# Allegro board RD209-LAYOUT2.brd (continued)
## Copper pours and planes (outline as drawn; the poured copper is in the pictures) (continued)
GND on TOP: outline of 2710 points within 0.43,0.41 198.5,157.02 ; 35 cut-outs
GND on TOP: 190.48,67.77 190.44,67.82 190.44,67.87 190.67,68.44 190.67,68.44 191.99,71.08 191.99,71.08 192.41,71.81 192.45,71.84 192.51,71.84 196.23,70.03 196.83,69.74 196.86,69.7 196.86,69.64 195.02,65.71 194.98,65.68 194.92,65.68
GND on TOP: 154.03,84.98 154,85.02 154,85.08 155.97,89.07 156.01,89.11 156.06,89.11 160.19,87.14 160.22,87.1 160.22,87.04 158.38,82.99 158.34,82.95 158.28,82.95
GND on TOP: 102.3,31.89 102.27,31.89 102.24,31.91 101.81,32.34 101.8,32.36 101.79,32.39 101.79,33.99 101.8,34.02 101.81,34.05 108.6,40.84 108.63,40.85 108.66,40.86 114.51,40.86 114.56,40.84 114.59,40.78 114.59,40.66 114.58,40.63 114.56,40.61 105.87,31.91 105.84,31.89 105.81,31.89 104.59,31.89 104.53,31.91 104.51,31.98 104.52,32.03 104.52,32.19 104.44,32.38 104.24,32.46 103.94,32.46 103.86,32.45 103.76,32.39 103.73,32.39 103.42,32.39 103.38,32.38 103.32,32.37 102.4,32.37 102.4,31.96 102.38,31.91 102.33,31.89
GND on TOP: 142.3,29.98 142.27,29.99 142.25,30 140.45,31.81 140.36,31.87 140.25,31.89 137.61,31.89 137.55,31.91 137.53,31.98 137.54,32.03 137.54,32.19 137.46,32.38 137.26,32.46 136.97,32.46 136.88,32.45 136.78,32.39 136.75,32.39 135.42,32.39 135.42,31.96 135.4,31.91 135.35,31.89 135.32,31.89 135.29,31.89 135.26,31.91 134.83,32.34 134.82,32.36 134.81,32.39 134.81,35.27 134.82,35.3 134.83,35.33 136.53,37.03 136.56,37.04 136.59,37.05 147.41,37.05 147.47,37.03 147.49,36.97 147.49,36.74 147.48,36.72 147.47,36.69 145.05,34.28 145.05,31.12 145.05,31.09 145.03,31.07 143.97,30 143.94,29.99 143.91,29.98
GND on BOTTOM: 0.43,116.42 0.43,116.45 0.43,116.47 19.63,156.98 19.67,157.02 19.73,157.02 204.21,69.57 204.25,69.53 204.25,69.47 174.35,6.38 174.32,6.35 174.28,6.34 99.98,0.41 99.95,0.42 19.31,38.63 19.28,38.65 19.27,38.68 ; 364 cut-outs
LED+1 on TOP: 108.5,22.09 108.5,27.48 112.94,27.48 112.94,22.09
LED+1 on TOP, CONDUCTIVE3: 70.72,66.22 70.72,70.34 77.07,70.34 77.07,66.22
LED+1 on CONDUCTIVE3: 108.5,22.09 108.5,27.48 112.87,27.48 112.87,22.09
LED+2 on TOP: 66.59,72.25 66.59,76.38 71.03,76.38 71.03,72.25
LED+2 on TOP: 74.21,22.09 74.21,27.48 79.92,27.48 79.92,22.09
LED+2 on BOTTOM: 74.28,22.09 74.23,22.11 74.21,22.16 74.21,27.41 74.23,27.46 74.28,27.48 78.26,27.48 78.32,27.46 78.34,27.41 78.34,22.16 78.32,22.11 78.26,22.09
LED+2 on BOTTOM: 66.66,72.25 66.61,72.27 66.59,72.32 66.59,75.67 66.61,75.72 66.66,75.74 70.96,75.74 71.01,75.72 71.03,75.67 71.03,72.32 71.01,72.27 70.96,72.25
LED+3 on TOP: 17.7,53.2 17.7,63.04 24.04,63.04 24.04,57.65 22.14,57.65 22.14,53.2
LED+3 on TOP, CONDUCTIVE2: 60.56,78.28 60.56,82.41 65,82.41 65,78.28
LED+3 on CONDUCTIVE2: 17.7,53.2 17.7,57.33 22.14,57.33 22.14,53.2
LED+4 on TOP: 54.53,84.31 54.53,88.44 58.97,88.44 58.97,84.31
LED+4 on TOP: 11.34,77.33 11.34,87.17 17.7,87.17 17.7,81.77 15.79,81.77 15.79,77.33
LED+4 on BOTTOM: 54.85,84.57 54.8,84.59 54.78,84.64 54.78,88.11 54.8,88.17 54.85,88.19 58.64,88.19 58.69,88.17 58.72,88.11 58.72,84.64 58.69,84.59 58.64,84.57
LED+4 on BOTTOM: 11.42,77.33 11.37,77.35 11.34,77.4 11.34,81.38 11.37,81.44 11.42,81.46 15.71,81.46 15.77,81.44 15.79,81.38 15.79,77.4 15.77,77.35 15.71,77.33
LED+5 on TOP: 48.49,90.35 48.49,94.47 52.94,94.47 52.94,90.35
LED+5 on TOP, BOTTOM: 5.63,108.44 5.63,113.84 10.07,113.84 10.07,108.44
LED+5 on BOTTOM: 48.49,90.35 48.49,94.47 51.67,94.47 51.67,90.35
LED+6 on TOP, CONDUCTIVE2: 42.46,96.38 42.46,100.51 46.91,100.51 46.91,96.38
LED+6 on TOP, CONDUCTIVE2: 11.98,135.12 11.98,140.51 16.43,140.51 16.43,135.12
LED+7 on TOP, CONDUCTIVE2: 141.52,22.09 141.52,27.48 145.97,27.48 145.97,22.09
LED+7 on TOP, CONDUCTIVE2: 90.72,46.53 90.72,50.66 95.16,50.66 95.16,46.53
LED-1 on TOP: 137.39,17.64 137.39,21.45 143.74,21.45 143.74,17.64
LED-1 on TOP, CONDUCTIVE3: 137.71,66.22 137.71,70.34 142.16,70.34 142.16,66.22
LED-1 on CONDUCTIVE3: 137.39,17.64 137.39,21.45 141.84,21.45 141.84,17.64
LED-2 on TOP: 131.68,72.25 131.68,76.38 136.12,76.38 136.12,72.25
LED-2 on TOP: 104.37,17.64 104.37,21.45 110.72,21.45 110.72,17.64
LED-2 on BOTTOM: 104.69,17.64 104.69,21.45 108.5,21.45 108.5,17.64
LED-2 on BOTTOM: 131.68,72.25 131.68,75.74 136.12,75.74 136.12,72.25
LED-3 on TOP, CONDUCTIVE2: 125.65,78.28 125.65,82.41 130.09,82.41 130.09,78.28
LED-3 on TOP, CONDUCTIVE2: 48.49,53.2 48.49,57.01 52.94,57.01 52.94,53.2
LED-4 on TOP: 42.14,77.33 42.14,81.14 48.49,81.14 48.49,77.33
LED-4 on TOP: 119.61,84.31 119.61,88.44 124.06,88.44 124.06,84.31
LED-4 on BOTTOM: 119.69,84.31 119.63,84.34 119.61,84.39 119.61,88.37 119.63,88.42 119.69,88.44 123.98,88.44 124.04,88.42 124.06,88.37 124.06,84.39 124.04,84.34 123.98,84.31
LED-4 on BOTTOM: 42.22,77.33 42.16,77.35 42.14,77.4 42.14,79.79 42.16,79.85 42.22,79.87 47.47,79.87 47.52,79.85 47.54,79.79 47.54,77.4 47.52,77.35 47.47,77.33
LED-5 on TOP, BOTTOM: 113.58,90.35 113.58,94.47 118.02,94.47 118.02,90.35
LED-5 on TOP, CONDUCTIVE3: 34.52,104 34.52,107.81 38.97,107.81 38.97,104
LED-6 on TOP: 40.87,130.67 40.87,134.48 47.22,134.48 47.22,130.67
LED-6 on TOP, CONDUCTIVE2: 107.55,96.38 107.55,100.51 111.99,100.51 111.99,96.38
LED-6 on CONDUCTIVE2: 40.87,130.67 40.87,134.48 45.32,134.48 45.32,130.67
LED-7 on TOP, CONDUCTIVE2: 153.27,46.53 153.27,50.66 157.71,50.66 157.71,46.53
LED-7 on TOP, CONDUCTIVE2: 170.41,17.64 170.41,21.45 174.86,21.45 174.86,17.64
N_16 on TOP: 111.99,17.64 111.99,21.45 115.48,21.45 115.48,27.48 118.34,27.48 118.34,22.09 116.44,22.09 116.44,17.64
N_16 on TOP, CONDUCTIVE3: 77.7,66.22 77.7,70.34 89.13,70.34 89.13,66.22
N_16 on CONDUCTIVE3: 111.99,17.64 111.99,21.45 116.44,21.45 116.44,17.64
N_20 on TOP: 117.07,17.64 117.07,21.45 120.56,21.45 120.56,27.48 123.42,27.48 123.42,22.09 121.52,22.09 121.52,17.64
N_20 on TOP, CONDUCTIVE3: 89.77,66.22 89.77,70.34 101.2,70.34 101.2,66.22
N_20 on CONDUCTIVE3: 117.07,17.64 117.07,21.45 121.52,21.45 121.52,17.64
N_23 on TOP: 122.15,17.64 122.15,21.45 125.65,21.45 125.65,27.48 128.5,27.48 128.5,22.09 126.6,22.09 126.6,17.64
N_23 on TOP, CONDUCTIVE3: 101.83,66.22 101.83,70.34 113.26,70.34 113.26,66.22
N_23 on CONDUCTIVE3: 122.15,17.64 122.15,21.45 126.6,21.45 126.6,17.64
N_26 on TOP: 127.23,17.64 127.23,21.45 130.72,21.45 130.72,27.48 133.58,27.48 133.58,22.09 131.68,22.09 131.68,17.64
N_26 on TOP, CONDUCTIVE3: 113.9,66.22 113.9,70.34 125.01,70.34 125.01,66.22
N_26 on CONDUCTIVE3: 127.23,17.64 127.23,21.45 131.68,21.45 131.68,17.64
N_29 on TOP: 71.67,72.25 71.67,76.38 83.1,76.38 83.1,72.25
N_29 on TOP: 78.97,17.64 78.97,21.45 82.47,21.45 82.47,27.48 85.32,27.48 85.32,22.09 83.42,22.09 83.42,17.64
N_29 on BOTTOM: 71.67,72.25 71.67,75.74 81.83,75.74 81.83,72.25
N_29 on BOTTOM: 79.29,17.64 79.29,21.45 83.1,21.45 83.1,17.64
N_30 on TOP: 132.31,17.64 132.31,21.45 135.81,21.45 135.81,27.48 138.66,27.48 138.66,22.09 136.76,22.09 136.76,17.64
N_30 on TOP, CONDUCTIVE3: 125.65,66.22 125.65,70.34 137.07,70.34 137.07,66.22
N_30 on CONDUCTIVE3: 132.31,17.64 132.31,21.45 136.76,21.45 136.76,17.64
N_39 on TOP: 84.05,17.64 84.05,21.45 87.55,21.45 87.55,27.48 90.4,27.48 90.4,22.09 88.5,22.09 88.5,17.64
N_39 on TOP: 83.73,72.25 83.73,76.38 95.16,76.38 95.16,72.25
N_39 on BOTTOM: 84.37,17.64 84.37,21.45 88.18,21.45 88.18,17.64
N_39 on BOTTOM: 85,72.25 85,75.74 93.89,75.74 93.89,72.25
N_42 on TOP: 89.13,17.64 89.13,21.45 92.62,21.45 92.62,27.48 95.48,27.48 95.48,22.09 93.58,22.09 93.58,17.64
N_42 on TOP: 95.8,72.25 95.8,76.38 107.23,76.38 107.23,73.14 107.22,73.08 107.22,72.25
N_42 on BOTTOM: 89.45,17.64 89.45,21.45 93.26,21.45 93.26,17.64
N_42 on BOTTOM: 95.8,72.25 95.8,75.74 105.96,75.74 105.96,72.25
N_45 on TOP: 107.86,72.25 107.86,76.38 118.98,76.38 118.98,72.25
N_45 on TOP: 94.21,17.64 94.21,21.45 97.7,21.45 97.7,27.48 100.56,27.48 100.56,22.09 98.66,22.09 98.66,17.64
N_45 on BOTTOM: 109.13,72.25 109.13,75.74 118.34,75.74 118.34,72.25
N_45 on BOTTOM: 94.53,17.64 94.53,21.45 98.34,21.45 98.34,17.64
N_48 on TOP: 99.29,17.64 99.29,21.45 102.78,21.45 102.78,27.48 105.64,27.48 105.64,22.09 103.74,22.09 103.74,17.64
N_48 on TOP: 119.61,72.25 119.61,76.38 131.04,76.38 131.04,72.25
N_48 on BOTTOM: 120.25,72.25 120.25,75.74 130.41,75.74 130.41,72.25
N_48 on BOTTOM: 99.61,17.64 99.61,21.45 103.42,21.45 103.42,17.64
N_57 on TOP: 23.09,53.2 23.09,57.01 26.58,57.01 26.58,63.04 29.44,63.04 29.44,57.65 27.54,57.65 27.54,53.2
N_57 on TOP, CONDUCTIVE2: 65.64,78.28 65.64,82.41 77.07,82.41 77.07,78.28
N_57 on CONDUCTIVE2: 23.09,53.2 23.09,57.01 27.54,57.01 27.54,53.2
N_60 on TOP: 28.17,53.2 28.17,57.01 31.67,57.01 31.67,63.04 34.52,63.04 34.52,57.65 32.62,57.65 32.62,53.2
N_60 on TOP, CONDUCTIVE2: 77.7,78.28 77.7,82.41 89.13,82.41 89.13,78.28
N_60 on CONDUCTIVE2: 28.17,53.2 28.17,57.01 32.62,57.01 32.62,53.2
N_63 on TOP: 89.77,78.28 89.77,82.41 101.2,82.41 101.2,79.22 101.19,79.21 101.17,79.15 101.16,79.08 101.16,78.28
N_63 on TOP: 33.25,53.2 33.25,57.01 36.75,57.01 36.75,63.04 39.6,63.04 39.6,57.65 37.7,57.65 37.7,53.2
N_63 on CONDUCTIVE2: 33.25,53.2 33.25,57.01 37.7,57.01 37.7,53.2
N_63 on CONDUCTIVE2: 89.77,78.28 89.77,82.41 101.2,82.41 101.2,78.28
N_66 on TOP: 38.33,53.2 38.33,57.01 41.83,57.01 41.83,63.04 44.68,63.04 44.68,57.65 42.78,57.65 42.78,53.2
N_66 on TOP, CONDUCTIVE2: 101.83,78.28 101.83,82.41 112.94,82.41 112.94,78.28
N_66 on CONDUCTIVE2: 38.33,53.2 38.33,57.01 42.78,57.01 42.78,53.2
N_69 on TOP: 43.41,53.2 43.41,57.01 46.91,57.01 46.91,63.04 49.76,63.04 49.76,57.65 47.86,57.65 47.86,53.2
N_69 on TOP, CONDUCTIVE2: 113.58,78.28 113.58,82.41 125.01,82.41 125.01,78.28
N_69 on CONDUCTIVE2: 43.41,53.2 43.41,57.01 47.86,57.01 47.86,53.2
N_78 on TOP: 16.74,77.33 16.74,81.14 20.23,81.14 20.23,87.17 23.09,87.17 23.09,81.77 21.19,81.77 21.19,77.33
N_78 on TOP, CONDUCTIVE3: 59.6,84.31 59.6,88.44 71.03,88.44 71.03,84.31
N_78 on CONDUCTIVE3: 16.74,77.33 16.74,81.14 21.19,81.14 21.19,77.33
N_81 on TOP: 71.67,84.31 71.67,88.44 83.1,88.44 83.1,85.14 83.09,85.08 83.09,84.31
N_81 on TOP: 21.82,77.33 21.82,81.14 25.32,81.14 25.32,87.17 28.17,87.17 28.17,81.77 26.27,81.77 26.27,77.33
N_81 on CONDUCTIVE2: 71.67,84.31 71.67,88.44 83.1,88.44 83.1,84.31
N_81 on CONDUCTIVE2: 21.82,77.33 21.82,81.14 26.27,81.14 26.27,77.33
N_84 on TOP: 83.73,84.31 83.73,88.44 95.16,88.44 95.16,85.26 95.11,85.18 95.09,85.08 95.09,84.31
N_84 on TOP: 26.9,77.33 26.9,81.14 30.39,81.14 30.39,87.17 33.25,87.17 33.25,81.77 31.35,81.77 31.35,77.33
N_84 on BOTTOM: 26.98,77.33 26.92,77.35 26.9,77.4 26.9,81.06 26.92,81.12 26.98,81.14 31.27,81.14 31.33,81.12 31.35,81.06 31.35,77.4 31.33,77.35 31.27,77.33
N_87 on TOP: 31.98,77.33 31.98,81.14 35.47,81.14 35.47,87.17 38.33,87.17 38.33,81.77 36.43,81.77 36.43,77.33
N_87 on TOP, CONDUCTIVE2: 95.8,84.31 95.8,88.44 106.91,88.44 106.91,84.31
N_87 on CONDUCTIVE3: 31.98,77.33 31.98,81.14 36.43,81.14 36.43,77.33
N_90 on TOP: 37.06,77.33 37.06,81.14 40.56,81.14 40.56,87.17 43.41,87.17 43.41,81.77 41.51,81.77 41.51,77.33
N_90 on TOP, CONDUCTIVE3: 107.55,84.31 107.55,88.44 118.98,88.44 118.98,84.31
N_90 on CONDUCTIVE3: 37.06,77.33 37.06,81.14 41.51,81.14 41.51,77.33
N_99 on TOP: 9.12,104 9.12,107.81 12.61,107.81 12.61,113.84 15.47,113.84 15.47,108.44 13.57,108.44 13.57,104
N_99 on TOP: 53.57,90.35 53.57,94.47 65,94.47 65,90.35
N_99 on BOTTOM: 55.48,90.35 55.48,94.47 65,94.47 65,90.35
N_99 on BOTTOM: 9.12,104 9.12,107.81 13.57,107.81 13.57,104
N_102 on TOP: 14.2,104 14.2,107.81 17.7,107.81 17.7,113.84 20.55,113.84 20.55,108.44 18.65,108.44 18.65,104
N_102 on TOP: 65.64,90.35 65.64,94.47 77.07,94.47 77.07,91.22 77.06,91.21 77.04,91.15 77.03,91.08 77.03,90.35
N_102 on BOTTOM: 14.2,104 14.2,107.81 18.65,107.81 18.65,104
N_102 on BOTTOM: 65.64,90.35 65.64,94.47 77.07,94.47 77.07,90.35
N_105 on TOP: 19.28,104 19.28,107.81 22.77,107.81 22.77,113.84 25.63,113.84 25.63,108.44 23.73,108.44 23.73,104
N_105 on TOP: 77.7,90.35 77.7,94.47 89.13,94.47 89.13,91.29 89.06,91.2 89.03,91.08 89.03,90.35
N_105 on BOTTOM: 77.7,90.35 77.7,94.47 89.13,94.47 89.13,90.35
N_105 on CONDUCTIVE3: 19.28,104 19.28,107.81 23.73,107.81 23.73,104
N_108 on TOP: 24.36,104 24.36,107.81 27.86,107.81 27.86,113.84 30.71,113.84 30.71,108.44 28.81,108.44 28.81,104
N_108 on TOP, CONDUCTIVE3: 89.77,90.35 89.77,94.47 100.88,94.47 100.88,90.35
N_108 on CONDUCTIVE3: 24.36,104 24.36,107.81 28.81,107.81 28.81,104
N_111 on TOP: 29.44,104 29.44,107.81 32.94,107.81 32.94,113.84 35.79,113.84 35.79,108.44 33.89,108.44 33.89,104
N_111 on TOP, BOTTOM: 101.52,90.35 101.52,94.47 112.94,94.47 112.94,90.35
N_111 on CONDUCTIVE3: 29.44,104 29.44,107.81 33.89,107.81 33.89,104
N_120 on TOP: 47.54,96.38 47.54,100.51 58.97,100.51 58.97,97.14 58.96,97.08 58.96,96.38
N_120 on TOP: 15.47,130.67 15.47,134.48 18.96,134.48 18.96,140.51 21.82,140.51 21.82,135.12 19.92,135.12 19.92,130.67
N_120 on CONDUCTIVE2: 47.54,96.38 47.54,100.51 58.97,100.51 58.97,96.38
N_120 on CONDUCTIVE2: 15.47,130.67 15.47,134.48 19.92,134.48 19.92,130.67
N_123 on TOP: 20.55,130.67 20.55,134.48 24.04,134.48 24.04,140.51 26.9,140.51 26.9,135.12 25,135.12 25,130.67
N_123 on TOP, CONDUCTIVE2: 59.6,96.38 59.6,100.51 70.72,100.51 70.72,96.38
N_123 on CONDUCTIVE2: 20.55,130.67 20.55,134.48 25,134.48 25,130.67
N_126 on TOP: 25.63,130.67 25.63,134.48 29.13,134.48 29.13,140.51 31.98,140.51 31.98,135.12 30.08,135.12 30.08,130.67
N_126 on TOP, CONDUCTIVE2: 71.35,96.38 71.35,100.51 82.78,100.51 82.78,96.38
N_126 on CONDUCTIVE2: 25.63,130.67 25.63,134.48 30.08,134.48 30.08,130.67
N_129 on TOP: 30.71,130.67 30.71,134.48 34.2,134.48 34.2,140.51 37.06,140.51 37.06,135.12 35.16,135.12 35.16,130.67
N_129 on TOP, CONDUCTIVE2: 83.42,96.38 83.42,100.51 94.85,100.51 94.85,96.38
N_129 on CONDUCTIVE2: 30.71,130.67 30.71,134.48 35.16,134.48 35.16,130.67
N_132 on TOP: 35.79,130.67 35.79,134.48 39.28,134.48 39.28,140.51 42.14,140.51 42.14,135.12 40.24,135.12 40.24,130.67
N_132 on TOP, CONDUCTIVE2: 95.48,96.38 95.48,100.51 106.91,100.51 106.91,96.38
N_132 on CONDUCTIVE2: 35.79,130.67 35.79,134.48 40.24,134.48 40.24,130.67
N_141 on TOP: 145.01,17.64 145.01,21.45 148.5,21.45 148.5,27.48 151.36,27.48 151.36,22.09 149.46,22.09 149.46,17.64
N_141 on TOP, CONDUCTIVE2: 95.8,46.53 95.8,50.66 106.59,50.66 106.59,46.53
N_141 on CONDUCTIVE2: 145.01,17.64 145.01,21.45 149.46,21.45 149.46,17.64
N_144 on TOP: 150.09,17.64 150.09,21.45 153.59,21.45 153.59,27.48 156.44,27.48 156.44,22.09 154.54,22.09 154.54,17.64
N_144 on TOP, CONDUCTIVE2: 107.23,46.53 107.23,50.66 118.02,50.66 118.02,46.53
N_144 on CONDUCTIVE2: 150.09,17.64 150.09,21.45 154.54,21.45 154.54,17.64
N_147 on TOP: 155.17,17.64 155.17,21.45 158.66,21.45 158.66,27.48 161.52,27.48 161.52,22.09 159.62,22.09 159.62,17.64
N_147 on TOP, CONDUCTIVE2: 118.66,46.53 118.66,50.66 129.45,50.66 129.45,46.53
N_147 on CONDUCTIVE2: 155.17,17.64 155.17,21.45 159.62,21.45 159.62,17.64
N_150 on TOP: 160.25,17.64 160.25,21.45 163.75,21.45 163.75,27.48 166.6,27.48 166.6,22.09 164.7,22.09 164.7,17.64
N_150 on TOP, CONDUCTIVE2: 130.09,46.53 130.09,50.66 141.2,50.66 141.2,46.53
N_150 on CONDUCTIVE2: 160.25,17.64 160.25,21.45 164.7,21.45 164.7,17.64
N_153 on TOP: 165.33,17.64 165.33,21.45 168.82,21.45 168.82,27.48 171.68,27.48 171.68,22.09 169.78,22.09 169.78,17.64
N_153 on TOP, CONDUCTIVE2: 141.84,46.53 141.84,50.66 152.63,50.66 152.63,46.53
N_153 on CONDUCTIVE2: 165.33,17.64 165.33,21.45 169.78,21.45 169.78,17.64

Small or netless copper shapes (teardrops, artwork), in the pictures only: 16 on TOP, 1 on BOTTOM

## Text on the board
Ref Des/Silkscreen Top: ZD26 | ZD27 | ZD32 | ZD20 | ZD28 | ZD33 | ZD21 | ZD14 | ZD29 | ZD34 | ZD22 | ZD15 | ZD30 | ZD35 | ZD23 | ZD16 | ZD31 | ZD36 | ZD24 | ZD17 | ZD37 | ZD25 | ZD18 | ZD19 | ZD8 | ZD9 | ZD10 | ZD11 | ZD12 | ZD13 | ZD2 | ZD3 | ZD4 | ZD5 | ZD6 | ZD7 | ZD38 | ZD39 | ZD40 | ZD41 | ZD42 | ZD43 | R70 | R71 | Q44 | R72 | R73 | R86 | R85 | R56 | R55 | Q54 | Q34 | R74 | R75 | R88 | R87 | Q24 | R58 | R57 | Q47 | R41 | R40 | R77 | R76 | Q37 | R90 | R89 | R60 | R59 | R43 | Q50 | Q57 | R42 | R79 | R78 | R92 | R91 | R62 | R61 | R45 | R44 | R81 | Q60 | Q27 | R94 | R93 | R80 | R64 | R63 | R47 | R46 | Q40 | R96 | R66 | Q30 | R95 | R49 | R48 | R65 | LED31 | R51 | R50 | LED25 | LED32 | LED19 | LED26 | LED13 | LED33 | LED20 | LED7 | LED27 | LED14 | LED1 | R26 | R25 | Q14 | LED34 | LED21 | LED8 | R28 | R27 | LED28 | LED15 | LED2 | R30 | R29 | Q17 | LED35 | LED37 | LED22 | LED9 | R32 | R31 | R34 | R33 | LED29 | LED16 | LED3 | Q20 | R36 | R35 | LED38 | LED36 | LED23 | LED10 | LED30 | LED17 | LED4 | R11 | R10 | Q4 | R13 | LED39 | R12 | LED24 | LED11 | R15 | R14 | LED18 | LED5 | Q7 | R17 | R16 | LED40 | LED12 | R19 | R18 | Q10 | LED6 | R21 | R20 | LED41 | R101 | R100 | Q64 | R103 | CON9 | R102 | LED42 | R104 | R105 | Q67 | R107 | R106 | R109 | R108 | Q70 | R110 | R111 | CON10 | Q43 | CON7 | Q45 | CON6 | Q53 | Q33 | Q46 | Q55 | CON5 | Q35 | Q23 | Q48 | Q56 | Q36 | Q25 | Q49 | Q58 | Q38 | Q26 | CON4 | Q51 | Q59 | Q39 | Q28 | Q61 | Q41 | Q29 | Q31 | Q13 | Q15 | Q16 | Q18 | Q19 | Q21 | Q3 | Q5 | Q6 | Q8 | Q9 | Q11 | Q63 | Q65 | Q66 | Q68 | Q69 | Q71 | CON3 | CON2 | CON8
